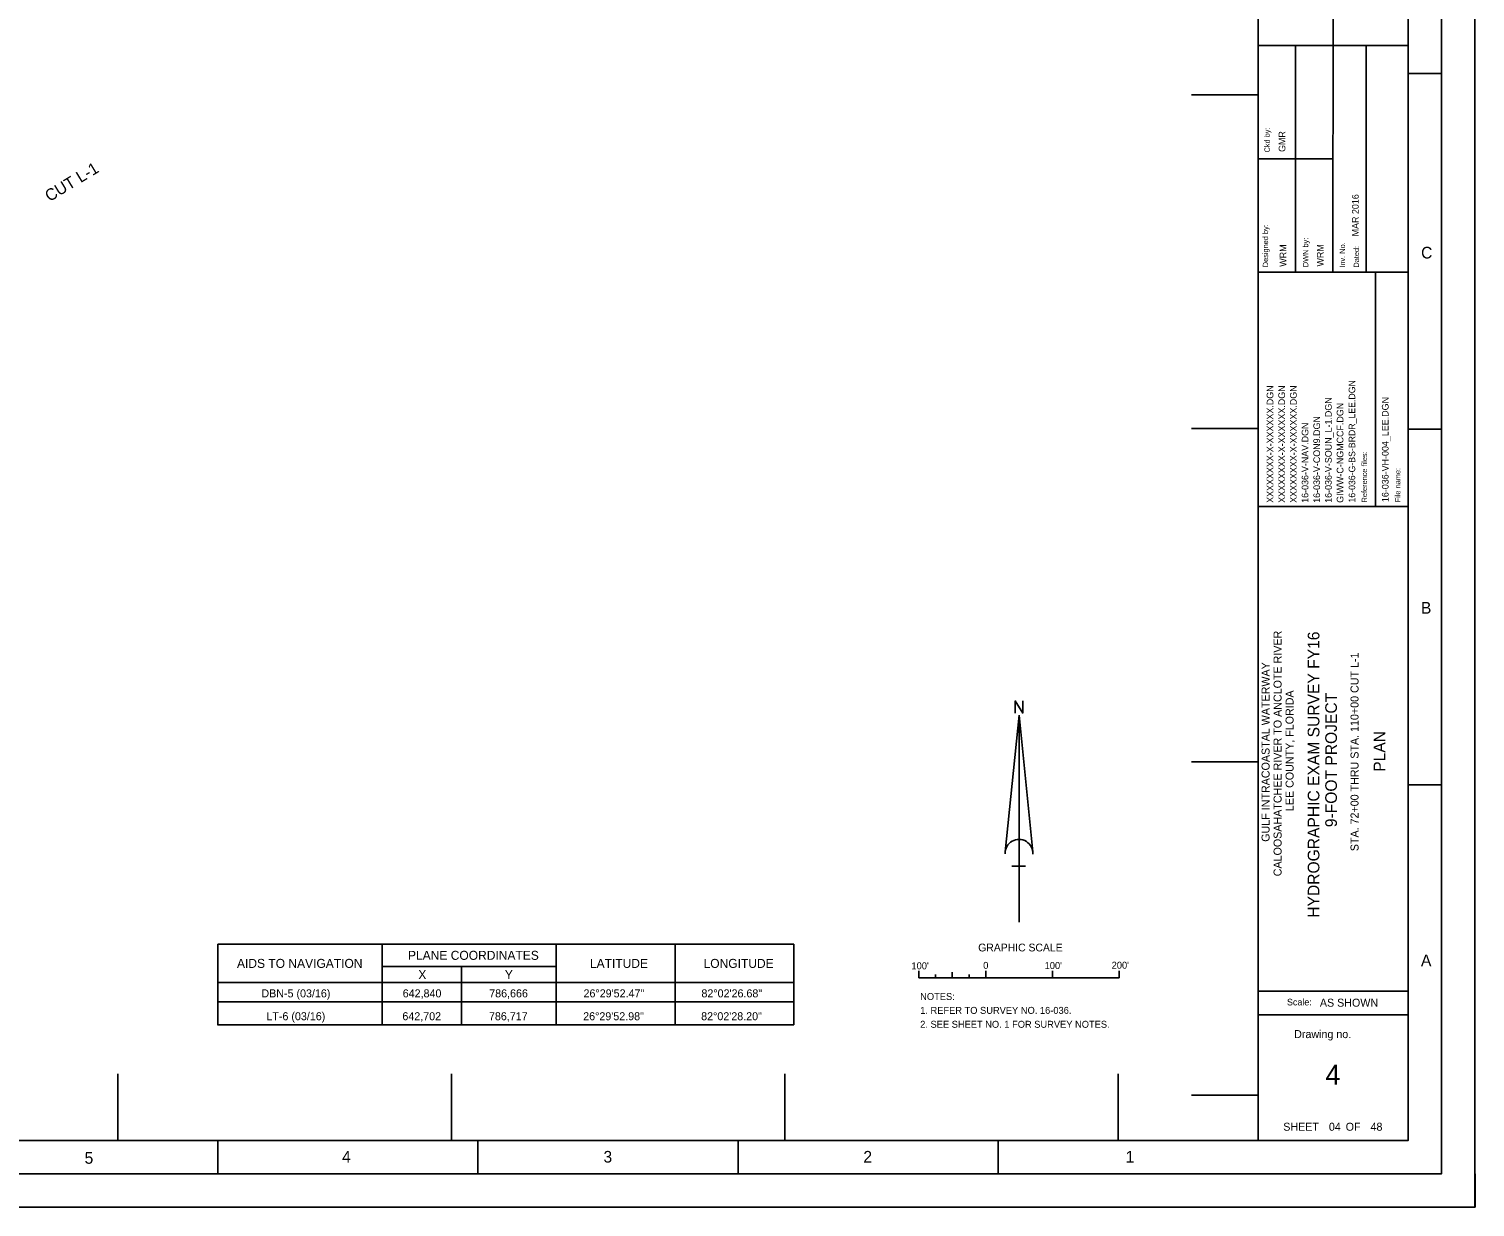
# Model space of a CAD drawing. Extents: x 640635 to 645035, y 784832 to 788232.
# Drawn here: x 642867 to 645035, y 784832 to 786599 of the extents above; entities that cross this region are included whole.
import ezdxf

# ---------------------------------------------------------------- set-up
doc = ezdxf.new("R2010")
doc.units = 0
for name, color, linetype in [('G-ANNO-NPLT', 7, 'Continuous'), ('G-ANNO-TEXT-DRWG', 7, 'Continuous'), ('G-ANNO-TEXT-PROJ', 7, 'Continuous'), ('G-ANNO-TEXT-TTLB', 7, 'Continuous'), ('G-ANNO-TTLB', 7, 'Continuous'), ('V-ANNO-NOTE', 7, 'Continuous'), ('V-ANNO-SCHD', 7, 'Continuous'), ('V-ANNO-SYMB', 7, 'Continuous'), ('V-CHAN-CNTR-IDEN', 7, 'Continuous'), ('V-TOPO-COOR-STAT', 7, 'Continuous')]:
    doc.layers.add(name, color=color, linetype=linetype)

msp = doc.modelspace()

# ---------------------------------------------------------------- linework, layer by layer
at = {"layer": 'G-ANNO-NPLT'}
msp.add_lwpolyline([(640634.9, 788232.2), (645034.9, 788232.2), (645034.9, 784832.2), (640634.9, 784832.2)], close=True, dxfattribs=at)
msp.add_lwpolyline([(645035, 784882.2), (645035, 784832.2), (644985, 784832.2)], dxfattribs=at)
at = {"layer": 'G-ANNO-TTLB'}
for p, q in [((644709.9, 788132.2), (644709.9, 784932.2)), ((644821.7, 786234.4), (644822.4, 787093.9)), ((644709.1, 786574), (644934.9, 786574)), ((644765.8, 786234.4), (644766, 786574)), ((644871.9, 786574), (644871.9, 786234.4)), ((644984.9, 786532.1), (644934.9, 786532.1)), ((644709.1, 786404.2), (644821.9, 786404.2)), ((644708.7, 786234.4), (644934.9, 786234.4)), ((644885.6, 786234.4), (644885.6, 785883)), ((644984.9, 785998.8), (644934.9, 785998.8)), ((644709.9, 785883), (644934.9, 785883)), ((644984.9, 785465.5), (644934.9, 785465.5)), ((644709.9, 785156), (644934.9, 785156)), ((644709.9, 785120.3), (644934.9, 785120.3)), ((643149.9, 784882.2), (643149.9, 784932.2)), ((643539.9, 784882.2), (643539.9, 784932.2)), ((643929.9, 784882.2), (643929.9, 784932.2)), ((644319.9, 784882.2), (644319.9, 784932.2))]:
    msp.add_line(p, q, dxfattribs=at)
for points in [[(640684.9, 784882.2), (644984.9, 784882.2), (644984.9, 788182.2), (640684.9, 788182.2)], [(644934.9, 788132.2), (640809.9, 788132.2), (640809.9, 784932.2), (644934.9, 784932.2)]]:
    msp.add_lwpolyline(points, close=True, dxfattribs=at)
at = {"layer": 'V-ANNO-NOTE'}
for p, q in [((644201.2, 785176), (644201.2, 785186.5)), ((644251.2, 785176), (644251.2, 785184.6)), ((644301.2, 785176), (644301.2, 785186.5)), ((644301.2, 785176), (644301.2, 785186.5)), ((644401.2, 785176), (644401.2, 785186.5)), ((644501.2, 785176), (644501.2, 785186.5)), ((644201.2, 785176), (644501.2, 785176)), ((644226.2, 785176), (644226.2, 785180.8)), ((644276.2, 785176), (644276.2, 785180.8)), ((644301.2, 785176), (644301.2, 785181))]:
    msp.add_line(p, q, dxfattribs=at)
at = {"layer": 'V-ANNO-SCHD'}
for p, q in [((643149.7, 785226.5), (644013.7, 785226.5)), ((643149.7, 785226.5), (643149.7, 785105.7)), ((643396.4, 785226.5), (643396.4, 785105.7)), ((643657.1, 785226.5), (643657.1, 785105.7)), ((643835.4, 785226.5), (643835.4, 785105.7)), ((644013.7, 785105.7), (644013.7, 785226.5)), ((643396.4, 785192.9), (643657.1, 785192.9)), ((643515.2, 785192.9), (643515.2, 785105.7)), ((643149.7, 785168.8), (644013.7, 785168.8)), ((643149.7, 785139.9), (644013.7, 785139.9)), ((643149.2, 785105.7), (644013.3, 785105.7))]:
    msp.add_line(p, q, dxfattribs=at)
at = {"layer": 'V-ANNO-SYMB'}
for p, q in [((644330.6, 785365), (644351.2, 785569.8)), ((644351.2, 785259.5), (644351.2, 785569.8)), ((644371.8, 785365), (644351.2, 785569.8)), ((644361, 785343.3), (644340.3, 785343.3))]:
    msp.add_line(p, q, dxfattribs=at)
msp.add_lwpolyline([(644345.5, 785573.1), (644345.5, 785591.2), (644356.8, 785573.1), (644356.8, 785591.2)], dxfattribs=at)
msp.add_arc((644351.2, 785362.9), 20.7, 355.2984, 182.0673, dxfattribs=at)
at = {"layer": 'V-TOPO-COOR-STAT'}
for p, q in [((644609.9, 786500), (644709.9, 786500)), ((644609.9, 786000), (644709.9, 786000)), ((644609.9, 785500), (644709.9, 785500)), ((643000, 784932.2), (643000, 785032.2)), ((643500, 784932.2), (643500, 785032.2)), ((644000, 784932.2), (644000, 785032.2)), ((644500, 784932.2), (644500, 785032.2)), ((644609.9, 785000), (644709.9, 785000))]:
    msp.add_line(p, q, dxfattribs=at)

# ---------------------------------------------------------------- texts
at = {"layer": 'G-ANNO-TEXT-DRWG'}
for s, height, p in [('GMR', 10, (644750.6, 786414.5)), ('WRM', 10, (644752.1, 786242.4)), ('WRM', 10, (644807.8, 786242.7)), ('XXXXXXXX-X-XXXXXX.DGN', 10, (644732.6, 785888.3)), ('XXXXXXXX-X-XXXXXX.DGN', 10, (644750.1, 785888.3)), ('XXXXXXXX-X-XXXXXX.DGN', 10, (644767.6, 785888.3)), ('16-036-V-SOUN_L-1.DGN', 10, (644820.1, 785888.3)), ('GIWW-C-NGMCCF.DGN', 10, (644837.6, 785888.3)), ('16-036-VH-004_LEE.DGN', 10, (644905.3, 785889.4)), ('16-036-V-NAV.DGN', 10, (644785.1, 785888.3)), ('16-036-V-CON9.DGN', 10, (644802.6, 785888.3)), ('STA. 72+00 THRU STA. 110+00 CUT L-1', 12, (644860.3, 785365.9)), ('PLAN', 17.5, (644900.5, 785485))]:
    msp.add_text(s, height=height, rotation=90, dxfattribs=at).set_placement(p)
for s, height, p in [('4', 30, (644810.8, 785016)), (' 04          48', 12, (644811.4, 784946.7))]:
    msp.add_text(s, height=height, dxfattribs=at).set_placement(p)
at = {"layer": 'G-ANNO-TEXT-PROJ'}
for s, height, p in [('MAR 2016', 10, (644860.6, 786287.9)), ('16-036-G-BS-BRDR_LEE.DGN', 9.8, (644855.3, 785888.7)), ('CALOOSAHATCHEE RIVER TO ANCLOTE RIVER', 12, (644744.9, 785328.3)), ('HYDROGRAPHIC EXAM SURVEY FY16', 17.5, (644801.6, 785266.1)), ('GULF INTRACOASTAL WATERWAY', 12, (644726.9, 785380)), ('LEE COUNTY, FLORIDA', 12, (644762.9, 785426)), ('9-FOOT PROJECT', 17.5, (644827.9, 785401.9))]:
    msp.add_text(s, height=height, rotation=90, dxfattribs=at).set_placement(p)
at = {"layer": 'G-ANNO-TEXT-TTLB'}
for s, p in [('Ckd by:', (644727.2, 786413.7)), ('Designed by:', (644724.7, 786241.6)), ('DWN by:', (644784.9, 786241.7)), ('Inv. No.', (644840.1, 786240.9)), ('Dated:', (644861, 786241)), ('Reference files:', (644873, 785888.8)), ('File name:', (644923, 785889))]:
    msp.add_text(s, height=8, rotation=90, dxfattribs=at).set_placement(p)
for s, height, p in [('Scale:', 10, (644753, 785134.6)), ('AS SHOWN', 12, (644802.3, 785132.7)), ('Drawing no.', 12, (644763.7, 785085.6)), ('SHEET         OF', 12, (644747.4, 784946.7))]:
    msp.add_text(s, height=height, dxfattribs=at).set_placement(p)
at = {"layer": 'G-ANNO-TTLB'}
for s, p in [('C', (644954.1, 786254.7)), ('B', (644953.9, 785722.1)), ('A', (644953.9, 785193.4)), ('5', (642950.1, 784897.2)), ('4', (643336.2, 784898.9)), ('3', (643728.1, 784898.9)), ('2', (644117.8, 784898.9)), ('1', (644511, 784898.9))]:
    msp.add_text(s, height=17.5, dxfattribs=at).set_placement(p)
at = {"layer": 'V-ANNO-NOTE'}
for s, height, p in [('GRAPHIC SCALE', 11.666, (644290, 785215.6)), ("100'", 10.42, (644189.9, 785188.8)), ('0', 10.4, (644297.5, 785189.5)), ("100'", 10.42, (644389.6, 785189.2)), ("200'", 10.42, (644490.1, 785189.7)), ('NOTES:', 10.42, (644203, 785142.8)), ('1. REFER TO SURVEY NO. 16-036.', 10.416, (644203, 785122)), ('2. SEE SHEET NO. 1 FOR SURVEY NOTES.', 10.416, (644203, 785101.1))]:
    msp.add_text(s, height=height, dxfattribs=at).set_placement(p)
at = {"layer": 'V-ANNO-SCHD'}
for s, height, p in [('AIDS TO NAVIGATION', 13.471, (643178.6, 785190.9)), ('PLANE COORDINATES', 13.471, (643435, 785203)), ('LATITUDE', 13.47, (643707.8, 785190.9)), ('LONGITUDE', 13.47, (643878.2, 785190.9)), ('X', 13.5, (643450.5, 785174.1)), ('Y', 13.5, (643580.2, 785174.1))]:
    msp.add_text(s, height=height, rotation=0.0001, dxfattribs=at).set_placement(p)
at = {"layer": 'V-ANNO-SYMB'}
for s, p in [('DBN-5 (03/16)', (643215.2, 785146.7)), ('642,840', (643427.1, 785146.7)), ('786,666', (643556.8, 785146.7)), ('26%%D29\'52.47"', (643698.2, 785146.7)), ('82%%D02\'26.68"', (643875, 785146.7)), ('LT-6 (03/16)', (643222.7, 785112.4)), ('642,702', (643426.6, 785112.4)), ('786,717', (643556.4, 785112.4)), ('26%%D29\'52.98"', (643697.7, 785112.4)), ('82%%D02\'28.20"', (643874.6, 785112.4))]:
    msp.add_text(s, height=12, dxfattribs=at).set_placement(p)
at = {"layer": 'V-CHAN-CNTR-IDEN'}
msp.add_text('CUT L-1', height=17.52, rotation=31.2715, dxfattribs=at).set_placement((642897.4, 786339.2))

doc.saveas('drawing.dxf')
